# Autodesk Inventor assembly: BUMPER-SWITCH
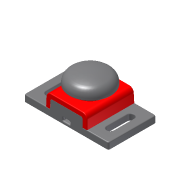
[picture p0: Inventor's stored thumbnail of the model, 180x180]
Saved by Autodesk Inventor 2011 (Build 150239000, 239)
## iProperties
Created: 2007-08
Part Number: BUMPER-SWITCH
Document SubType Name: Assembly
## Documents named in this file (5)
- C:\Data Folder\VEX 2011\Inventor Datasets\Unit 16\Components\BUMPER-SWITCH.iam
- C:\Data Folder\VEX 2011\Inventor Datasets\Unit 16\Components\BUMPER-SWITCH-TOP.ipt
- C:\Data Folder\VEX 2011\Inventor Datasets\Unit 16\Components\BUMPER-SWITCH-BOT.ipt
- C:\Data Folder\VEX 2011\Inventor Datasets\Unit 16\Components\BUMPER-SWITCH-INNER-HEAD.ipt
- C:\Data Folder\VEX 2011\Inventor Datasets\Unit 16\Components\BUMPER-SWITCH-HEAD.ipt
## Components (4 placed, 4 different names)
1. BUMPER-SWITCH-TOP
2. BUMPER-SWITCH-BOT
3. BUMPER-SWITCH-INNER-HEAD
4. BUMPER-SWITCH-HEAD
